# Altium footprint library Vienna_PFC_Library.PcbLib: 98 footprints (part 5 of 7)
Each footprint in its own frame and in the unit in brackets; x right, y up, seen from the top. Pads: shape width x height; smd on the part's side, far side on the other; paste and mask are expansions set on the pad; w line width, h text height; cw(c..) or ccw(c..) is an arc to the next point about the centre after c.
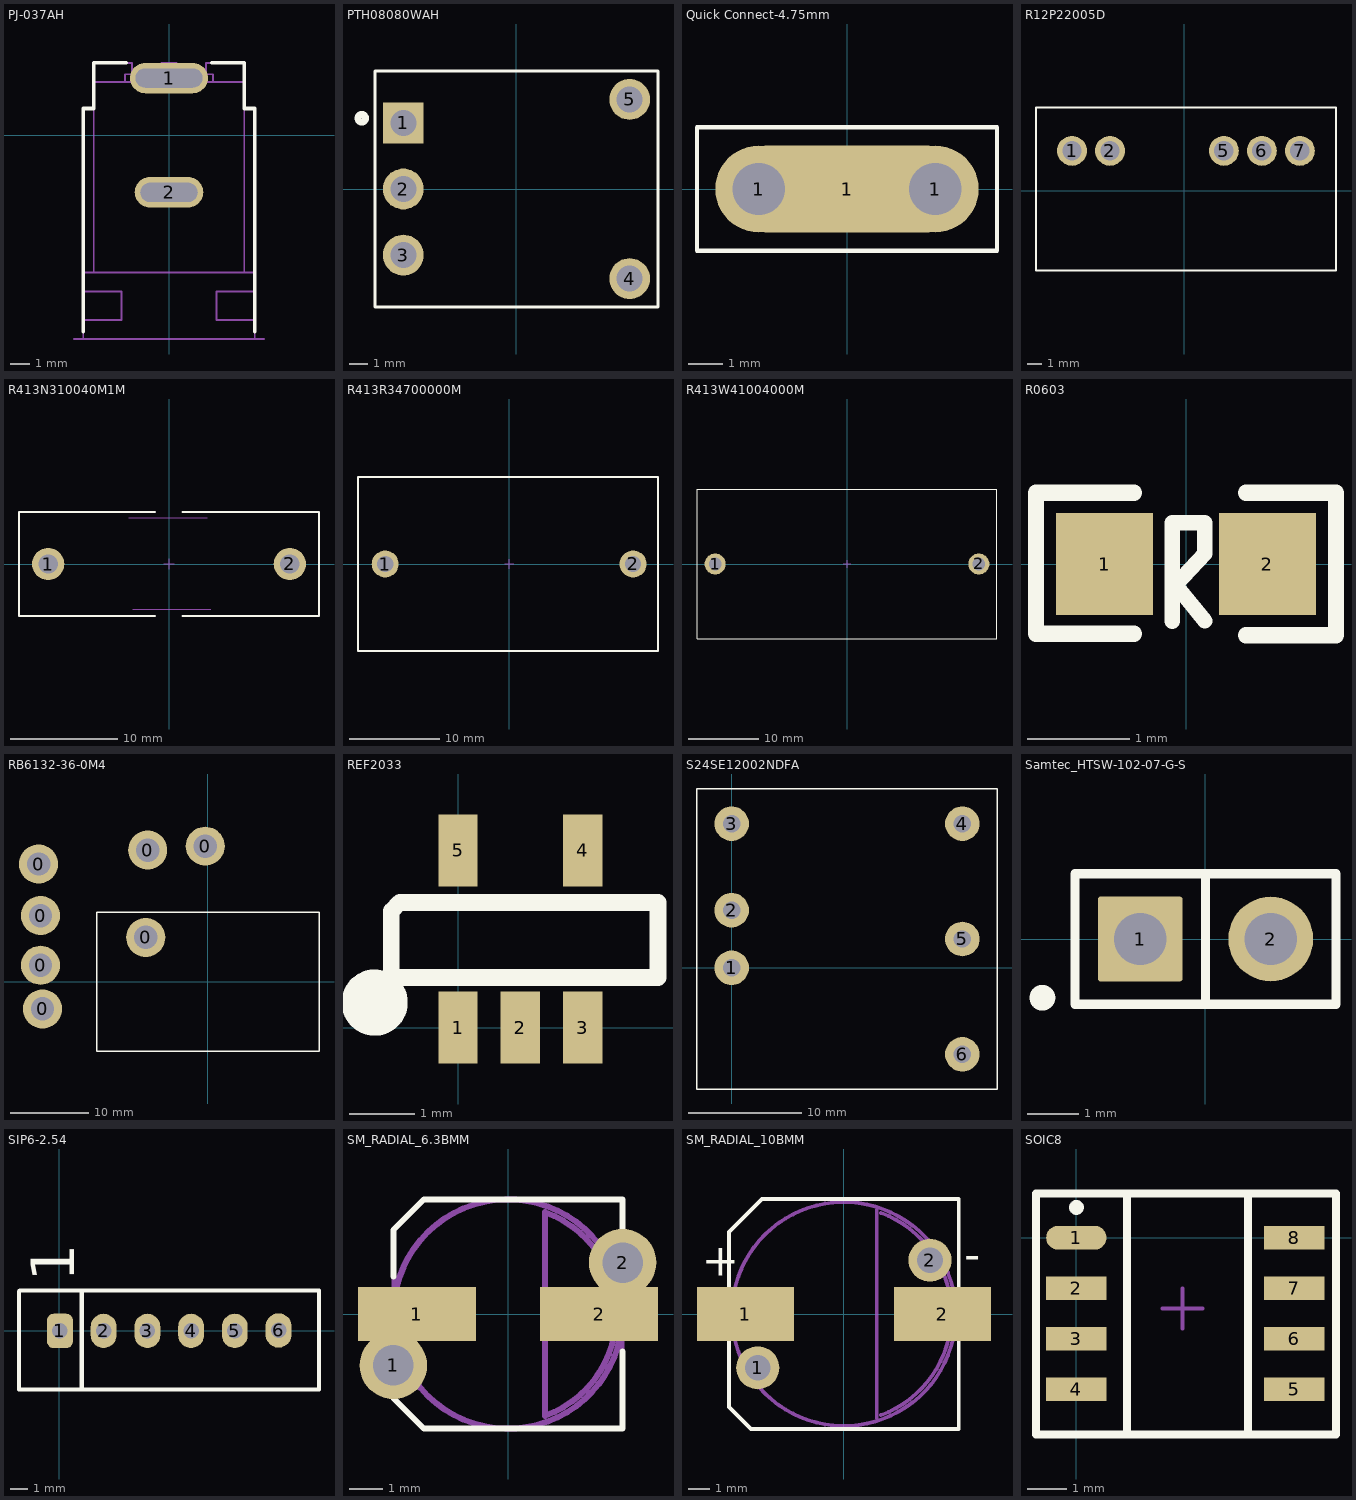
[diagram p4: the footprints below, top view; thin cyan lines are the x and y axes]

## PJ-037AH [mm] "Power Jack, 2mm, R/A, TH"
height 11.2
pads (2):
  oval 4.1x1.6 hole 1 slot 3.5 at 0 deg: 1(0,3)
  oval 3.6x1.6 hole 1 slot 3 at 0 deg: 2(0,-3)
Top Overlay:
  lines w0.2: -4.5,-10.3 -4.5,-9.7 -4.5,-8.2 -4.5,-7.2 -4.5,1.4 -3.95,1.4 -3.95,2.8 -3.95,3.8 -2.25,3.8 ; 2.25,3.8 3.95,3.8 3.95,2.8 3.95,1.4 4.5,1.4 4.5,-7.2 4.5,-8.2 4.5,-9.7 4.5,-10.3
Mechanical 1:
  lines w0.1: -5,-10.7 5,-10.7
Mechanical 5:
  lines w0.1: -3.95,-7.2 -3.95,1.4 ; -2.3,2.8 -2.3,3.2 2.3,3.2 2.3,2.8 ; -1.95,3.2 -1.95,3.8 -3.95,3.8 -3.95,2.8 ; -1.5,3.2 cw(c-1.3,3.2) -1.3,3.4 1.3,3.4 cw(c1.3,3.2) 1.5,3.2 ; -0.4,3.4 -0.4,3.656 -0.4,3.8 0.4,3.8 0.4,3.656 0.4,3.4 ; 1.95,3.2 1.95,3.8 3.95,3.8 3.95,2.8 ; 3.95,-7.2 3.95,1.4 ; -4.5,-9.7 -4.2,-9.7 -2.5,-9.7 -2.5,-8.2 -4.2,-8.2 -4.5,-8.2 ; -4.5,-9.7 -4.5,-8.2 ; -4.5,-9.7 -4.5,-10.7 -4.2,-10.7 4.2,-10.7 4.5,-10.7 4.5,-9.7 ; -4.5,-8.2 -4.5,-7.2 ; -4.5,-7.2 -4.2,-7.2 4.2,-7.2 4.5,-7.2 ; -4.5,-7.2 -4.5,1.4 -3.95,1.4 ; -3.95,1.4 -3.95,2.8 ; -3.95,2.8 3.95,2.8 ; 3.95,1.4 3.95,2.8 ; 3.95,1.4 4.5,1.4 4.5,-7.2 ; 4.5,-9.7 4.2,-9.7 2.5,-9.7 2.5,-8.2 4.2,-8.2 4.5,-8.2 ; 4.5,-9.7 4.5,-8.2 ; 4.5,-8.2 4.5,-7.2
3D body "PJ-037AH.stp": height 11, standoff -3.5, extent -4.5,-10.7 4.5,3.8

## PTH08080WAH [mm]
height 8.179
pads (5):
  rect 2.2x2.2 hole 1.4: 1(-6.096,3.556)
  round 2.2 hole 1.4: 2(-6.096,0) 3(-6.096,-3.556) 4(6.096,-4.826) 5(6.096,4.826)
Top Overlay:
  circle w0.381: c-8.331,3.81 r0.203
  lines w0.178: -7.62,-6.35 -7.62,6.35 7.62,6.35 7.62,-6.35 -7.62,-6.35
Mechanical 5:
  lines w0.102: -7.62,-6.35 -7.62,6.35 7.62,6.35 7.62,-6.35 -7.62,-6.35
3D body: height 1.52, standoff -3.56, extent 5.59,4.319 6.602,5.333
3D body: height 1.52, standoff -3.56, extent 5.59,-5.333 6.602,-4.319
3D body: height 1.52, standoff -3.56, extent -6.6,3.049 -5.588,4.063
3D body: height 1.52, standoff -3.56, extent -6.6,-0.507 -5.588,0.507
3D body: height 1.52, standoff -3.56, extent -6.602,-4.063 -5.59,-3.049
3D body: height 8.18, standoff 0.25, extent -7.619,-6.349 7.619,6.349

## Quick Connect-4.75mm [mm] "Quick Connect-4.75mm"
height 8.7
pads (3):
  round 2.5 hole 1.5: 1(-2.54,0) 1(2.54,0)
  rrect50% 6x2.5 smd: 1(0,0)
Top Overlay:
  lines w0.127: -4.318,-1.778 -4.318,1.778 4.318,1.778 4.318,-1.778 -4.318,-1.778
3D body: height 9, standoff 0, extent -3.81,-1.27 3.81,1.27

## R12P22005D [mm]
height 12.5
pads (5):
  round 2 hole 1.3: 1(-7.498,2.68) 2(-4.958,2.68) 5(2.662,2.68) 6(5.202,2.68) 7(7.742,2.68)
Top Overlay:
  lines w0.127: -9.906,-5.334 10.16,-5.334 10.16,5.588 -9.906,5.588 -9.906,-5.334
3D body: height 12.5, standoff 0, extent -9.398,-4.826 9.652,5.08

## R413N310040M1M [mm] "Capacitor"
height 17
pads (2):
  round 3 hole 1.8: 1(-11.25,0) 2(11.25,0)
Top Overlay:
  lines w0.178: -1.319,-4.826 -13.97,-4.826 -13.97,4.826 -1.319,4.826 ; 1.27,-4.826 13.97,-4.826 13.97,4.826 1.27,4.826
Mechanical 15:
  lines w0.1: -3.744,4.318 3.556,4.318 ; -3.396,-4.212 3.904,-4.212 ; -0.5,0 0.5,0 ; 0,-0.5 0,0.5
3D body "R413N310040M1M.step": height 17.1, standoff -35, extent -13.462,-4.353 13.338,4.353

## R413R34700000M [mm] "Capacitor"
height 33
pads (2):
  round 3 hole 1.8: 1(-13.75,0) 2(13.75,0)
Top Overlay:
  lines w0.178: -16.764,-9.652 16.51,-9.652 16.51,9.652 -16.764,9.652 -16.764,-9.652
Mechanical 15:
  lines w0.1: -0.5,0 0.5,0 ; 0,-0.5 0,0.5
3D body "R413R34700000M.step": height 33.1, standoff -6, extent -16.129,-9.103 16.171,9.103

## R413W41004000M [mm] "Capacitor"
height 41.5
pads (2):
  round 3 hole 1.8: 1(-18.75,0) 2(18.75,0)
Top Overlay:
  lines w0.178: -21.336,-10.668 -21.336,10.668 21.336,10.668 21.336,-10.668 -21.336,-10.668
Mechanical 15:
  lines w0.1: -0.5,0 0.5,0 ; 0,-0.5 0,0.5
3D body "R413W41004000M.step": height 40.1, standoff -35, extent -20.972,-10.152 20.828,10.152

## R0603 [mm]
height 1.45
pads (2):
  rect 0.95x1 smd: 1(-0.8,0) 2(0.8,0)
Top Overlay:
  lines w0.15: -0.135,-0.562 -0.135,0.406 0.185,0.406 0.185,0.33 0.185,0.178 0.185,0.102 -0.102,-0.203 0.185,-0.559
  lines w0.16: -0.51,-0.686 -1.473,-0.686 -1.473,0.7 -0.51,0.7 ; 0.59,-0.7 1.473,-0.7 1.473,0.7 0.59,0.7

## RB6132-36-0M4 [mm] "Common mode choke"
height 52
pads (7):
  round 5 hole 3: 0(-21.666,15.088) 0(-21.412,2.134) 0(-21.412,8.484) 0(-21.158,-3.454) 0(-7.95,5.69) 0(-7.696,16.866) 0(-0.33,17.374)
Top Overlay:
  lines w0.178: -14.224,-8.89 14.224,-8.89 14.224,8.89 -14.224,8.89 -14.224,-8.89
3D body "EW60-1A3-BL12D04,00000.stp": height 11.9, standoff -5.3, extent -18.4,-34.4 18.4,0

## REF2033 [mm]
pads (5):
  rect 0.6x1.1 smd: 1(0,0) 2(0.95,0) 3(1.9,0) 4(1.9,2.7) 5(0,2.7)
Top Overlay:
  circle w0.5: c-1.27,0.381 r0.254
  lines w0.254: -1.016,0.762 3.048,0.762 3.048,1.905 -0.889,1.905 -1.016,1.778 -1.016,0.762
3D body "DBV0005A.stp": height 1.09, standoff 0, extent -0.508,0 2.413,2.845

## S24SE12002NDFA [mil]
height 401.57
pads (6):
  round 120 hole 60: 1(0,0) 2(0,200) 3(0,500) 4(800,500) 5(800,100) 6(800,-300)
Top Overlay:
  lines w5: -120,-420 -120,620 920,620 920,-420 -120,-420
3D body: height 401.57, standoff 0, extent -120,-420 920,620

## Samtec_HTSW-102-07-G-S [mm] "Samtec 100mil, 1x2, 230 mil above insulator"
height 8.382
pads (2):
  rrect6% 1.65x1.65 hole 1.016: 1(-1.27,0)
  round 1.65 hole 1.016: 2(1.27,0)
Top Overlay:
  circle w0.25: c-3.173,-1.143 r0.125
  lines w0.178: 0,-1.27 0,1.27 ; -2.54,-1.27 -2.54,1.27 2.54,1.27 2.54,-1.27 -2.54,-1.27
Mechanical 5:
  lines w0.127: -2.54,-1.27 2.54,-1.27 2.54,1.27 -2.54,1.27 -2.54,-1.27
3D body: height 8.38, standoff -2.03, extent 0.953,-0.317 1.587,0.317
3D body: height 8.38, standoff -2.03, extent -1.587,-0.317 -0.953,0.317
3D body: height 2.54, standoff 0, extent -2.539,-1.269 2.539,1.269

## SIP6-2.54 [mm]
height 1.45
pads (6):
  rrect50% 1.5x2 hole 0.9: 1(0.025,0)
  oval 1.5x2 hole 0.9: 2(2.565,0) 3(5.105,0) 4(7.645,0) 5(10.185,0) 6(12.725,0.025)
Top Overlay:
  lines w0.254: 1.295,-3.404 1.295,2.311 ; -2.35,-3.4 15.075,-3.4 15.075,2.35 -2.311,2.35 -2.35,2.311 -2.35,-3.4
  text "1" at 0.864,2.845 h2.52

## SM_RADIAL_6.3BMM [mm] "Nichicon 6.3x7.7"
height 8
pads (4):
  round 2 hole 1.2: 1(-3.4,-1.524) 2(3.4,1.524)
  rect 3.5x1.6 smd: 1(-2.7,0) 2(2.7,0)
Top Overlay:
  lines w0.178: -3.4,-1.122 -3.4,-2.493 -2.493,-3.4 3.4,-3.4 3.4,-1.112 ; -3.4,1.108 -3.4,2.493 -2.493,3.4 3.4,3.4 3.4,1.118
Mechanical 5:
  lines w0.127: -3.4,-2.493 -2.493,-3.4 3.4,-3.4 3.4,3.4 -2.493,3.4 -3.4,2.493 -3.4,-2.493
Mechanical 13:
  circle w0.178: c0,0 r3.4
  lines w0.178: 1.1,-3.022 ccw(c0,0) 1.1,3.022 1.1,-3.022
3D body: height 8, standoff 6, extent 1.1,-3.023 3.217,3.023
3D body: height 8, standoff 1, extent -3.399,-3.399 3.399,3.399
3D body: height 1, standoff 0, extent -3.401,-3.401 3.401,3.401

## SM_RADIAL_10BMM [mm] "Nichicon 10x10.5"
height 10.5
pads (4):
  rect 4.5x2.5 smd: 1(-4.572,0) 2(4.572,0)
  round 2 hole 1.2: 1(-4,-2.5) 2(4,2.5)
Top Overlay:
  lines w0.178: -5.334,-1.122 -5.334,-4.318 -4.318,-5.334 5.334,-5.334 5.334,-1.112 ; -5.334,1.108 -5.334,3.81 -3.81,5.334 5.334,5.334 5.334,1.118
  text "-" at 5.588,2.032 h1.52
  text "+" at -6.604,1.778 h1.52
Mechanical 5:
  lines w0.127: -5.334,-4.318 -4.318,-5.334 5.334,-5.334 5.334,5.334 -3.81,5.334 -5.334,3.81 -5.334,-4.318
Mechanical 13:
  circle w0.178: c0,0 r5.2
  lines w0.178: 1.524,4.826 1.526,-4.826 ; 1.71,-4.698 ccw(c0,0) 1.71,4.698
3D body: height 10.5, standoff 6, extent 1.524,-5.08 4.942,4.826
3D body: height 10.5, standoff 1, extent -5.088,-5.121 4.902,5.088
3D body: height 1, standoff 0, extent -5.386,-5.334 5.386,5.334

## SOIC8 [mm]
height 1
pads (8):
  oval 1.52x0.6 smd: 1(0,0)
  rect 1.52x0.6 smd: 2(0,-1.27) 3(0,-2.54) 4(0,-3.81) 5(5.48,-3.81) 6(5.48,-2.54) 7(5.48,-1.27) 8(5.48,0)
Top Overlay:
  circle w0.3: c0,0.762 r0.036
  lines w0.2: -1.016,-4.953 -1.016,1.118 6.528,1.118 6.528,-4.953 -1.016,-4.953 ; 1.267,-4.953 1.267,1.118 4.318,1.118 4.318,-4.953 1.267,-4.953
Mechanical 13:
  lines w0.1: 1.267,-4.953 1.267,1.118 4.318,1.118 4.318,-4.953 1.267,-4.953
Mechanical 15:
  lines w0.1: 2.167,-1.778 3.167,-1.778 ; 2.667,-2.278 2.667,-1.278
3D body: height 1.7, standoff 0, extent 1.267,-4.826 4.318,1.016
